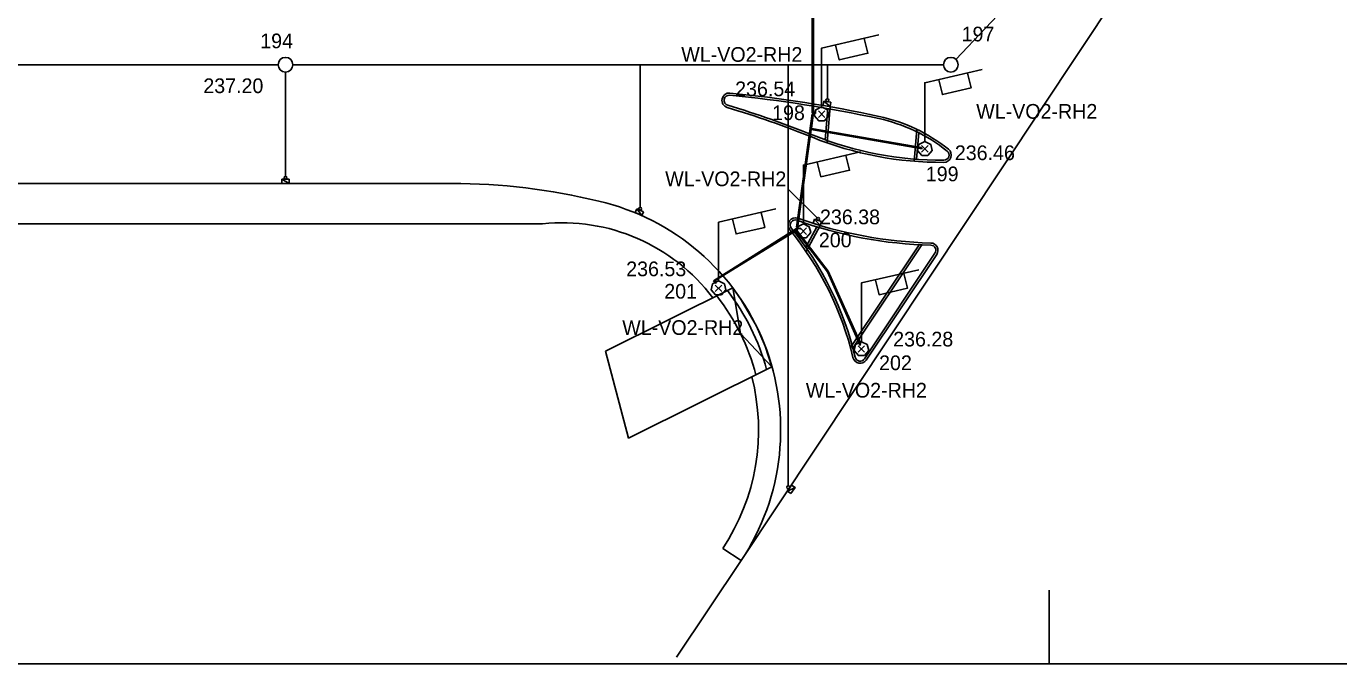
# Model space of a CAD drawing. Extents: x -264222 to -263592, y -1242345 to -1242048.
# Drawn here: x -263871.6 to -263782.2, y -1242344.9 to -1242301.5 of the extents above; entities that cross this region are included whole.
import ezdxf

# ---------------------------------------------------------------- set-up
doc = ezdxf.new("R2010")
doc.units = 0
for name, color, linetype in [('BOD_CISLO', 7, 'Continuous'), ('BOD_SYMBOL', 7, 'Continuous'), ('BOD_VYSKA', 7, 'Continuous'), ('KFA_2D_SITUACIA_DSP', 7, 'Continuous'), ('KFA_SO_62-1_VO_LAMPY_MERANE', 7, 'Continuous'), ('KFA_SO_62-1_VO_POPIS_LAMP_PROJEKT', 7, 'Continuous'), ('KFA_SO_62-1_VO_TRASA_KABLOV_PROJEKT', 7, 'Continuous'), ('RAM_NA_TLAC_1-500', 7, 'Continuous')]:
    doc.layers.add(name, color=color, linetype=linetype)

msp = doc.modelspace()

# ---------------------------------------------------------------- linework, layer by layer
at = {"layer": 'BOD_SYMBOL'}
for p, q in [((-263817.616, -1242307.735), (-263817.174, -1242307.293)), ((-263817.174, -1242307.735), (-263817.616, -1242307.293)), ((-263810.585, -1242310.098), (-263810.143, -1242309.656)), ((-263810.143, -1242310.098), (-263810.585, -1242309.656)), ((-263818.861, -1242315.699), (-263818.419, -1242315.257)), ((-263818.419, -1242315.699), (-263818.861, -1242315.257)), ((-263824.638, -1242319.59), (-263824.196, -1242319.148)), ((-263824.196, -1242319.59), (-263824.638, -1242319.148)), ((-263814.904, -1242323.728), (-263814.462, -1242323.286)), ((-263814.462, -1242323.728), (-263814.904, -1242323.286))]:
    msp.add_line(p, q, dxfattribs=at)
at = {"layer": 'KFA_2D_SITUACIA_DSP'}
for p, q in [((-263822.88, -1242337.914), (-263734.49, -1242204.937)), ((-263780.353, -1242274.236), (-263808.248, -1242303.783)), ((-263854.415, -1242304.147), (-263903.413, -1242304.147)), ((-263809.091, -1242304.153), (-263853.415, -1242304.148)), ((-263829.755, -1242313.856), (-263829.755, -1242304.151)), ((-263819.667, -1242332.824), (-263819.667, -1242304.147)), ((-263817.005, -1242306.465), (-263817.005, -1242304.152)), ((-263853.915, -1242311.749), (-263853.915, -1242304.647)), ((-263817.296, -1242306.914), (-263817.252, -1242306.627)), ((-263817.252, -1242306.627), (-263817.296, -1242306.914)), ((-263816.802, -1242306.99), (-263817.296, -1242306.914)), ((-263817.296, -1242306.914), (-263816.802, -1242306.99)), ((-263817.252, -1242306.627), (-263816.757, -1242306.703)), ((-263816.802, -1242306.99), (-263817.252, -1242306.627)), ((-263816.802, -1242306.99), (-263817.252, -1242306.627)), ((-263816.964, -1242307.132), (-263817.145, -1242309.262)), ((-263816.803, -1242307.008), (-263817.012, -1242309.468)), ((-263816.757, -1242306.703), (-263816.802, -1242306.99)), ((-263810.912, -1242308.547), (-263811.097, -1242310.721)), ((-263810.781, -1242308.779), (-263810.935, -1242310.583)), ((-263980.94, -1242312.232), (-263857.327, -1242312.232)), ((-263842.601, -1242312.24), (-263924.192, -1242312.232)), ((-263854.165, -1242311.949), (-263853.665, -1242311.949)), ((-263854.165, -1242312.239), (-263854.165, -1242311.949)), ((-263854.165, -1242311.949), (-263853.665, -1242312.239)), ((-263854.165, -1242311.949), (-263853.665, -1242312.239)), ((-263853.665, -1242311.949), (-263854.165, -1242311.949)), ((-263853.665, -1242312.239), (-263854.165, -1242312.239)), ((-263853.665, -1242311.949), (-263853.665, -1242312.239)), ((-263853.665, -1242312.239), (-263853.665, -1242311.949)), ((-263817.708, -1242314.574), (-263819.667, -1242312.615)), ((-263830.101, -1242314.219), (-263829.983, -1242313.954)), ((-263829.983, -1242313.954), (-263830.101, -1242314.219)), ((-263829.645, -1242314.423), (-263830.101, -1242314.219)), ((-263830.101, -1242314.219), (-263829.645, -1242314.423)), ((-263829.983, -1242313.954), (-263829.527, -1242314.158)), ((-263829.645, -1242314.423), (-263829.983, -1242313.954)), ((-263829.645, -1242314.423), (-263829.983, -1242313.954)), ((-263829.527, -1242314.158), (-263829.645, -1242314.423)), ((-264038.443, -1242314.982), (-263836.403, -1242314.982)), ((-263818.469, -1242316.58), (-263817.711, -1242315.183)), ((-263818.453, -1242316.866), (-263817.491, -1242315.093)), ((-263817.966, -1242314.94), (-263817.874, -1242314.665)), ((-263817.874, -1242314.665), (-263817.966, -1242314.94)), ((-263817.492, -1242315.099), (-263817.966, -1242314.94)), ((-263817.966, -1242314.94), (-263817.492, -1242315.099)), ((-263817.874, -1242314.665), (-263817.4, -1242314.824)), ((-263817.492, -1242315.099), (-263817.874, -1242314.665)), ((-263817.492, -1242315.099), (-263817.874, -1242314.665)), ((-263817.4, -1242314.824), (-263817.492, -1242315.099)), ((-263810.751, -1242316.405), (-263815.43, -1242323.41)), ((-263810.576, -1242316.414), (-263815.268, -1242323.437)), ((-263809.676, -1242316.98), (-263814.48, -1242324.171)), ((-263809.551, -1242317.064), (-263814.356, -1242324.254)), ((-263823.444, -1242319.346), (-263832.112, -1242323.652)), ((-263813.542, -1242320.69), (-263813.542, -1242320.69)), ((-263813.542, -1242320.69), (-263813.542, -1242320.69)), ((-263832.112, -1242323.652), (-263830.544, -1242329.573)), ((-263820.775, -1242324.719), (-263830.544, -1242329.573)), ((-263819.723, -1242333.187), (-263819.444, -1242332.772)), ((-263819.723, -1242333.187), (-263819.203, -1242332.933)), ((-263819.203, -1242332.933), (-263819.482, -1242333.349)), ((-263819.444, -1242332.772), (-263819.203, -1242332.933)), ((-263819.482, -1242333.349), (-263819.723, -1242333.187)), ((-263824.127, -1242337.081), (-263822.88, -1242337.914)), ((-263827.28, -1242344.5), (-263822.88, -1242337.914))]:
    msp.add_line(p, q, dxfattribs=at)
for points in [[(-263832.112, -1242323.652), (-263830.544, -1242329.573), (-263820.775, -1242324.719), (-263821.24, -1242323.31), (-263821.84, -1242321.938), (-263822.869, -1242320.154), (-263823.444, -1242319.346), (-263832.112, -1242323.652)], [(-263823.444, -1242319.346), (-263822.93, -1242322.44), (-263820.775, -1242324.719)]]:
    msp.add_lwpolyline(points, dxfattribs=at)
msp.add_lwpolyline([(-263819.723, -1242333.187), (-263819.203, -1242332.933), (-263819.444, -1242332.772)], close=True, dxfattribs=at)
for centre, radius in [((-263853.915, -1242304.147), 0.5), ((-263808.591, -1242304.147), 0.5), ((-263817.005, -1242306.565), 0.1), ((-263853.915, -1242311.849), 0.1), ((-263829.755, -1242313.956), 0.1), ((-263817.637, -1242314.644), 0.1), ((-263819.667, -1242332.924), 0.1)]:
    msp.add_circle(centre, radius, dxfattribs=at)
for centre, radius, start, end in [((-263823.686, -1242306.574), 0.5, 84.50312, 253.37264), ((-263823.686, -1242306.574), 0.35, 84.50312, 253.37264), ((-263832, -1242392.966), 87.141, 77.74517, 84.50312), ((-263832, -1242392.966), 87.291, 77.74517, 84.50312), ((-263842.678, -1242370.168), 65.869, 68.01969, 73.37264), ((-263842.678, -1242370.168), 66.019, 68.01969, 73.37264), ((-263815.913, -1242318.902), 11.35, 51.49122, 77.74517), ((-263815.913, -1242318.902), 11.5, 51.49122, 77.74517), ((-263809.228, -1242287.295), 23.35, 248.01969, 270.4085), ((-263809.228, -1242287.295), 23.5, 248.01969, 270.4085), ((-263809.064, -1242310.295), 0.35, 270.4085, 51.49122), ((-263809.064, -1242310.295), 0.5, 270.4085, 51.49122), ((-263842.427, -1242353.351), 41.111, 76.13622, 90.24149), ((-263836.184, -1242329.025), 16, 326.2529, 76.96946), ((-263835.045, -1242327.715), 12.805, 36.92053, 96.08735), ((-263819.181, -1242315.066), 0.5, 70.28283, 219.38571), ((-263819.181, -1242315.066), 0.35, 70.28283, 219.38571), ((-263809.228, -1242287.295), 29.15, 250.28283, 268.56407), ((-263809.228, -1242287.295), 29, 250.28283, 268.56407), ((-263836.184, -1242329.025), 21.5, 13.26701, 39.38571), ((-263836.184, -1242329.025), 21.65, 13.26701, 39.38571), ((-263809.967, -1242316.786), 0.35, 326.2529, 88.56407), ((-263809.967, -1242316.786), 0.5, 326.2529, 88.56407), ((-263836.184, -1242329.025), 15.6, 15.3332, 37.50818), ((-263836.184, -1242329.025), 14.8, 14.72564, 38.11574), ((-263836.184, -1242329.025), 21.65, 13.26701, 14.95961), ((-263814.771, -1242323.977), 0.5, 193.26701, 326.2529), ((-263814.771, -1242323.977), 0.35, 193.26701, 326.2529), ((-263836.228, -1242329.021), 14.539, 326.33444, 14.41665)]:
    msp.add_arc(centre, radius, start, end, dxfattribs=at)
at = {"layer": 'KFA_SO_62-1_VO_LAMPY_MERANE'}
for p, q in [((-263817.445, -1242307.514), (-263817.345, -1242307.514)), ((-263817.395, -1242307.514), (-263817.395, -1242307.514)), ((-263810.414, -1242309.877), (-263810.314, -1242309.877)), ((-263810.364, -1242309.877), (-263810.364, -1242309.877)), ((-263818.69, -1242315.478), (-263818.59, -1242315.478)), ((-263818.64, -1242315.478), (-263818.64, -1242315.478)), ((-263824.467, -1242319.369), (-263824.367, -1242319.369)), ((-263824.417, -1242319.369), (-263824.417, -1242319.369)), ((-263814.733, -1242323.507), (-263814.633, -1242323.507)), ((-263814.683, -1242323.507), (-263814.683, -1242323.507))]:
    msp.add_line(p, q, dxfattribs=at)
for points in [[(-263817.395, -1242307.014), (-263817.795, -1242307.214), (-263817.895, -1242307.614), (-263817.595, -1242307.964), (-263817.195, -1242307.964), (-263816.895, -1242307.614), (-263816.995, -1242307.214), (-263817.395, -1242307.014), (-263817.395, -1242303.014), (-263813.495, -1242302.114)], [(-263814.495, -1242302.364), (-263814.245, -1242303.364), (-263816.195, -1242303.814), (-263816.445, -1242302.814)], [(-263810.364, -1242309.377), (-263810.764, -1242309.577), (-263810.864, -1242309.977), (-263810.564, -1242310.327), (-263810.164, -1242310.327), (-263809.864, -1242309.977), (-263809.964, -1242309.577), (-263810.364, -1242309.377), (-263810.364, -1242305.377), (-263806.464, -1242304.477)], [(-263807.464, -1242304.727), (-263807.214, -1242305.727), (-263809.164, -1242306.177), (-263809.414, -1242305.177)], [(-263818.64, -1242314.978), (-263819.04, -1242315.178), (-263819.14, -1242315.578), (-263818.84, -1242315.928), (-263818.44, -1242315.928), (-263818.14, -1242315.578), (-263818.24, -1242315.178), (-263818.64, -1242314.978), (-263818.64, -1242310.978), (-263814.74, -1242310.078)], [(-263815.74, -1242310.328), (-263815.49, -1242311.328), (-263817.44, -1242311.778), (-263817.69, -1242310.778)], [(-263824.417, -1242318.869), (-263824.817, -1242319.069), (-263824.917, -1242319.469), (-263824.617, -1242319.819), (-263824.217, -1242319.819), (-263823.917, -1242319.469), (-263824.017, -1242319.069), (-263824.417, -1242318.869), (-263824.417, -1242314.869), (-263820.517, -1242313.969)], [(-263821.517, -1242314.219), (-263821.267, -1242315.219), (-263823.217, -1242315.669), (-263823.467, -1242314.669)], [(-263814.683, -1242323.007), (-263815.083, -1242323.207), (-263815.183, -1242323.607), (-263814.883, -1242323.957), (-263814.483, -1242323.957), (-263814.183, -1242323.607), (-263814.283, -1242323.207), (-263814.683, -1242323.007), (-263814.683, -1242319.007), (-263810.783, -1242318.107)], [(-263811.783, -1242318.357), (-263811.533, -1242319.357), (-263813.483, -1242319.807), (-263813.733, -1242318.807)]]:
    msp.add_lwpolyline(points, dxfattribs=at)
at = {"layer": 'KFA_SO_62-1_VO_TRASA_KABLOV_PROJEKT'}
for p, q in [((-263818.045, -1242300.744), (-263818.045, -1242307.43)), ((-263817.945, -1242307.399), (-263817.945, -1242300.75)), ((-263818.045, -1242307.5), (-263819.095, -1242315.2)), ((-263818.08, -1242308.487), (-263817.945, -1242307.399)), ((-263818.045, -1242307.43), (-263817.76, -1242307.43)), ((-263817.76, -1242307.43), (-263818.045, -1242307.5)), ((-263819.05, -1242315.45), (-263818.1, -1242308.562)), ((-263818.1, -1242308.562), (-263810.55, -1242309.88)), ((-263810.622, -1242309.785), (-263818.08, -1242308.487)), ((-263810.55, -1242309.88), (-263810.622, -1242309.785)), ((-263819.095, -1242315.2), (-263818.823, -1242315.313)), ((-263819.095, -1242315.3), (-263824.751, -1242318.854)), ((-263824.645, -1242318.85), (-263819.145, -1242315.45)), ((-263819.145, -1242315.45), (-263816.995, -1242318.25)), ((-263818.823, -1242315.313), (-263819.095, -1242315.3)), ((-263816.94, -1242318.193), (-263819.05, -1242315.45)), ((-263816.995, -1242318.25), (-263814.766, -1242323.256)), ((-263814.745, -1242323.1), (-263816.94, -1242318.193)), ((-263824.751, -1242318.854), (-263824.606, -1242319.052)), ((-263824.606, -1242319.052), (-263824.645, -1242318.85)), ((-263814.766, -1242323.256), (-263814.745, -1242323.1))]:
    msp.add_line(p, q, dxfattribs=at)
at = {"layer": 'RAM_NA_TLAC_1-500'}
msp.add_line((-263801.898, -1242344.938), (-263801.898, -1242339.938), dxfattribs=at)
msp.add_lwpolyline([(-264221.898, -1242344.938), (-263591.898, -1242344.938), (-263591.898, -1242047.938), (-264221.898, -1242047.938)], close=True, dxfattribs=at)

# ---------------------------------------------------------------- texts
at = {"layer": 'BOD_CISLO'}
for s, p in [('197', (-263807.857, -1242302.556)), ('194', (-263855.637, -1242303.022)), ('198', (-263820.766, -1242307.918)), ('199', (-263810.297, -1242312.081)), ('200', (-263817.583, -1242316.578)), ('201', (-263828.115, -1242320.074)), ('202', (-263813.48, -1242324.943))]:
    msp.add_text(s, height=1, dxfattribs=at).set_placement(p)
at = {"layer": 'BOD_VYSKA'}
for s, p in [('237.20', (-263859.515, -1242306.078)), ('236.54', (-263823.285, -1242306.289)), ('236.46', (-263808.319, -1242310.641)), ('236.38', (-263817.505, -1242315.008)), ('236.53', (-263830.707, -1242318.547)), ('236.28', (-263812.52, -1242323.331))]:
    msp.add_text(s, height=1, dxfattribs=at).set_placement(p)
at = {"layer": 'KFA_SO_62-1_VO_POPIS_LAMP_PROJEKT'}
for p in [(-263826.955, -1242303.946), (-263806.862, -1242307.821), (-263828.049, -1242312.416), (-263830.977, -1242322.543), (-263818.471, -1242326.811)]:
    msp.add_text('WL-VO2-RH2', height=1, dxfattribs=at).set_placement(p)

doc.saveas('drawing.dxf')
